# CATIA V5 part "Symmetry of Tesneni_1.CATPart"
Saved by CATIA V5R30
Part number: Symmetry of Tesneni_1
Bounding box of the stored display mesh (mm): x 0 to 1.2, y -6 to 6, z -6 to 6
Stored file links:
  E:\Bakalarka\Model\Forma_v7\Symmetry of Tesneni_1.CATPart
  E:\Bakalarka\Model\Forma_v7\Tesneni.CATPart
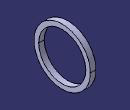
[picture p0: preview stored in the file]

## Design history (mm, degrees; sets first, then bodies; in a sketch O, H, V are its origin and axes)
Body1 (main body)
  Body2 "Body from original PartBody"
    Solid1: linked copy from another document
  Assemble1: tool Body2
